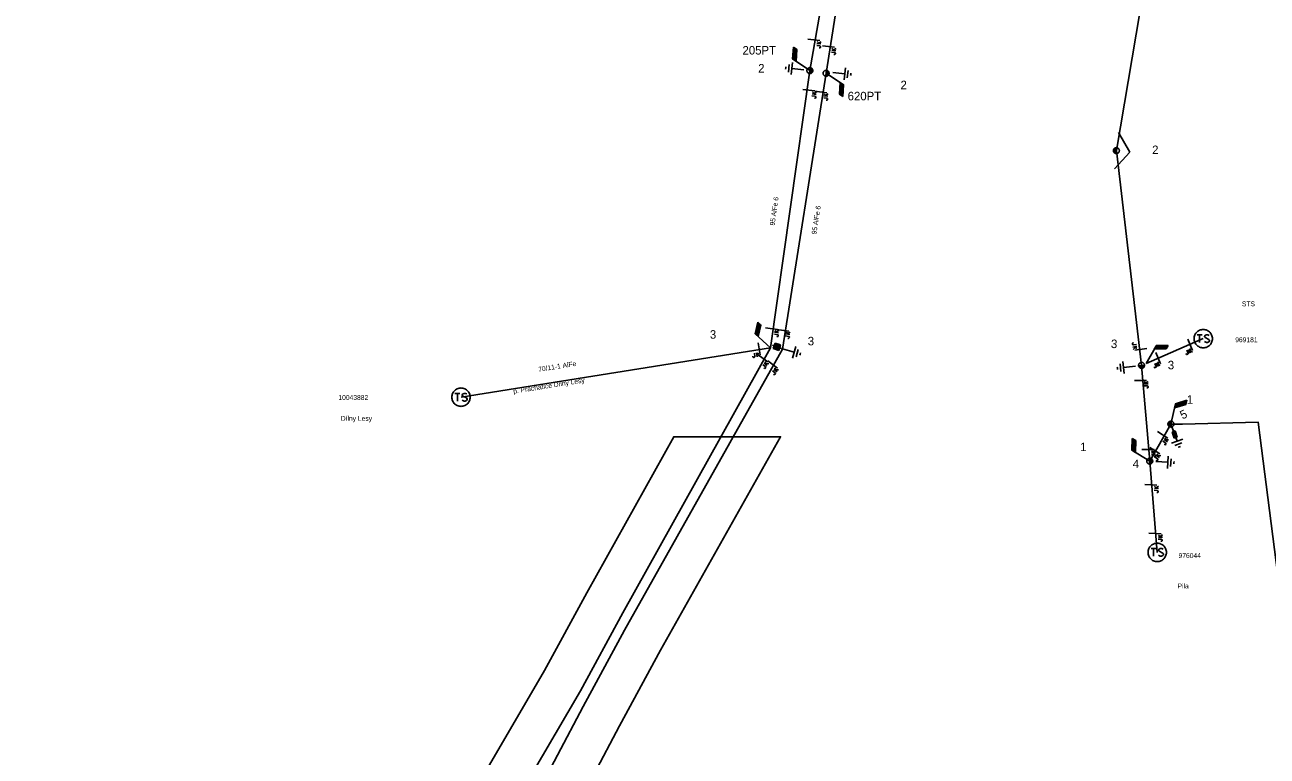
# Model space of a CAD drawing. Extents: x -788491 to -785797, y -1154753 to -1152002.
# Drawn here: x -787760.5 to -787504.8, y -1153999.5 to -1153849 of the extents above; entities that cross this region are included whole.
import ezdxf

# ---------------------------------------------------------------- set-up
doc = ezdxf.new("R2010")
doc.units = 0
for name, color, linetype in [('Default', 7, 'Continuous'), ('Vrstva 1', 7, 'Continuous'), ('Vrstva 11', 7, 'Continuous'), ('Vrstva 12', 7, 'Continuous'), ('Vrstva 13', 7, 'Continuous'), ('Vrstva 14', 7, 'Continuous'), ('Vrstva 15', 7, 'Continuous'), ('Vrstva 16', 7, 'Continuous'), ('Vrstva 18', 7, 'Continuous'), ('Vrstva 2', 7, 'Continuous'), ('Vrstva 25', 7, 'Continuous'), ('Vrstva 26', 7, 'Continuous'), ('Vrstva 27', 7, 'Continuous'), ('Vrstva 35', 7, 'Continuous'), ('Vrstva 4', 7, 'Continuous'), ('Vrstva 5', 7, 'Continuous'), ('Vrstva 52', 7, 'Continuous'), ('Vrstva 57', 7, 'Continuous'), ('Vrstva 59', 7, 'Continuous'), ('Vrstva 6', 7, 'Continuous')]:
    doc.layers.add(name, color=color, linetype=linetype)

# ---------------------------------------------------------------- blocks, each defined once
blk = doc.blocks.new('VN840')
at = {"layer": 'Vrstva 15'}
for points in [[(-0.01, 1.41), (-0.01, -1.09)], [(-1.51, -1.24), (-1.51, -1.15)], [(-1.48, -1.35), (-1.51, -1.24)], [(-1.33, -1.42), (-1.48, -1.35)], [(-1.27, -1.42), (-1.33, -1.42)], [(-1.13, -1.35), (-1.27, -1.42)], [(-1.09, -1.24), (-1.13, -1.35)], [(-1.09, -0.59), (-1.09, -1.24)], [(-0.68, -0.59), (-0.68, -1.42)], [(-0.68, -1.11), (-0.27, -0.59)], [(-0.54, -0.94), (-0.2, -1.42)]]:
    blk.add_lwpolyline(points, dxfattribs=at)
blk = doc.blocks.new('VN860')
at = {"layer": 'Vrstva 15'}
for points in [[(-3.74, 0), (0.01, 2.82)], [(0.01, 2.82), (3.76, 0)]]:
    blk.add_lwpolyline(points, dxfattribs=at)
blk = doc.blocks.new('VN440')
at = {"layer": 'Vrstva 2'}
for points in [[(1.22, 0), (1.21, 0.13), (1.19, 0.25), (1.16, 0.38), (1.11, 0.5), (1.05, 0.61), (0.98, 0.72), (0.9, 0.82), (0.81, 0.91), (0.71, 0.99), (0.6, 1.06), (0.49, 1.12), (0.37, 1.16), (0.25, 1.2), (0.12, 1.22), (-0.01, 1.22), (-0.14, 1.22), (-0.26, 1.2), (-0.39, 1.16), (-0.51, 1.12), (-0.62, 1.06), (-0.73, 0.99), (-0.83, 0.91), (-0.92, 0.82), (-1, 0.72), (-1.07, 0.61), (-1.13, 0.5), (-1.18, 0.38), (-1.21, 0.25), (-1.23, 0.13), (-1.24, 0), (-1.23, -0.13), (-1.21, -0.26), (-1.18, -0.38), (-1.13, -0.5), (-1.07, -0.62), (-1, -0.73), (-0.92, -0.83), (-0.83, -0.92), (-0.73, -1), (-0.62, -1.07), (-0.51, -1.13), (-0.39, -1.17), (-0.26, -1.2), (-0.14, -1.23), (-0.01, -1.23), (0.12, -1.23), (0.25, -1.2), (0.37, -1.17), (0.49, -1.13), (0.6, -1.07), (0.71, -1), (0.81, -0.92), (0.9, -0.83), (0.98, -0.73), (1.05, -0.62), (1.11, -0.5), (1.16, -0.38), (1.19, -0.26), (1.21, -0.13), (1.22, 0)], [(-1.24, 0), (1.22, 0)], [(-1.18, -0.34), (1.1, -0.34)], [(-1.01, -0.63), (0.97, -0.63)], [(-0.74, -0.92), (0.68, -0.92)]]:
    blk.add_lwpolyline(points, dxfattribs=at)
blk = doc.blocks.new('VN820')
at = {"layer": 'Vrstva 13'}
for points in [[(0, 0), (0, -2.1)], [(-0.32, -1.63), (0.34, -1.63)], [(-0.32, -2.95), (-0.32, -1.63)], [(0, -2.1), (-0.12, -1.86)], [(0, -2.1), (0.12, -1.86)], [(0.34, -1.63), (0.34, -2.95)], [(0.34, -2.95), (-0.32, -2.95)], [(0, -2.95), (0, -3.75)]]:
    blk.add_lwpolyline(points, dxfattribs=at)
blk = doc.blocks.new('VN810')
at = {"layer": 'Vrstva 14'}
for points in [[(0, -1.25), (0, -3.75)], [(1.25, -3.75), (-1.25, -3.75)], [(0.77, -4.37), (-0.8, -4.37)], [(0, -5), (-0.25, -5)], [(0.27, -5), (0, -5)]]:
    blk.add_lwpolyline(points, dxfattribs=at)
blk = doc.blocks.new('VN610')
at = {"layer": 'Vrstva 6'}
for points in [[(1.88, 0), (1.87, 0.2), (1.84, 0.39), (1.79, 0.58), (1.72, 0.77), (1.63, 0.94), (1.52, 1.11), (1.4, 1.26), (1.26, 1.4), (1.1, 1.53), (0.94, 1.63), (0.76, 1.72), (0.58, 1.8), (0.39, 1.85), (0.19, 1.88), (-0.01, 1.89), (-0.21, 1.88), (-0.4, 1.85), (-0.59, 1.8), (-0.78, 1.72), (-0.95, 1.63), (-1.12, 1.53), (-1.27, 1.4), (-1.41, 1.26), (-1.54, 1.11), (-1.64, 0.94), (-1.73, 0.77), (-1.8, 0.58), (-1.86, 0.39), (-1.89, 0.2), (-1.9, 0), (-1.89, -0.2), (-1.86, -0.39), (-1.8, -0.58), (-1.73, -0.77), (-1.64, -0.95), (-1.54, -1.11), (-1.41, -1.27), (-1.27, -1.41), (-1.12, -1.53), (-0.95, -1.64), (-0.78, -1.73), (-0.59, -1.8), (-0.4, -1.85), (-0.21, -1.88), (-0.01, -1.89), (0.19, -1.88), (0.39, -1.85), (0.58, -1.8), (0.76, -1.73), (0.94, -1.64), (1.1, -1.53), (1.26, -1.41), (1.4, -1.27), (1.52, -1.11), (1.63, -0.95), (1.72, -0.77), (1.79, -0.58), (1.84, -0.39), (1.87, -0.2), (1.88, 0)], [(-1.27, 0.78), (-0.26, 0.78)], [(-0.76, 0.78), (-0.76, -0.79)], [(1.19, 0.66), (0.94, 0.78), (0.62, 0.78), (0.37, 0.66), (0.24, 0.47), (0.24, 0.4), (0.37, 0.22), (1.12, -0.16), (1.25, -0.32), (1.25, -0.48), (1.12, -0.67), (0.87, -0.79), (0.62, -0.79), (0.49, -0.73), (0.24, -0.6)]]:
    blk.add_lwpolyline(points, dxfattribs=at)
blk = doc.blocks.new('VN001')
at = {"layer": 'Default'}
for p, q in [((1.73, 3.03), (4.14, 3.03)), ((1.76, 3.08), (4.17, 3.08)), ((1.79, 3.13), (4.2, 3.13)), ((1.82, 3.18), (4.23, 3.18)), ((1.85, 3.23), (4.26, 3.23)), ((1.87, 3.28), (4.29, 3.28)), ((1.9, 3.33), (4.32, 3.33)), ((1.93, 3.38), (4.35, 3.38)), ((1.96, 3.43), (4.37, 3.43)), ((1.99, 3.48), (4.4, 3.48)), ((2.02, 3.53), (4.43, 3.53)), ((2.05, 3.58), (4.46, 3.58)), ((2.07, 3.63), (4.49, 3.63)), ((2.1, 3.68), (4.52, 3.68)), ((2.13, 3.73), (2.54, 3.73))]:
    blk.add_line(p, q, dxfattribs=at)
blk.add_lwpolyline([(2.13, 3.73), (0, 0)], dxfattribs=at)
blk.add_lwpolyline([(4.55, 3.73), (2.13, 3.73), (1.7, 2.98), (4.12, 2.99)], close=True, dxfattribs=at)
blk = doc.blocks.new('VN470')
at = {"layer": 'Vrstva 2'}
for points in [[(-1.23, 1.22), (1.23, 1.22)], [(-1.23, -1.23), (-1.23, 1.22)], [(-0.92, 0.9), (0.92, 0.9)], [(-0.92, -0.95), (-0.92, 0.9)], [(-0.61, 0.61), (0.61, 0.61)], [(-0.61, -0.62), (-0.61, 0.61)], [(-0.31, -0.27), (-0.31, 0.34)], [(-0.31, 0.34), (0.31, 0.34)], [(0, 1.22), (0, 1.97)], [(0.31, 0.34), (0.31, -0.27)], [(0.61, 0.61), (0.61, -0.62)], [(0.92, 0.9), (0.92, -0.95)], [(1.23, 1.22), (1.23, -1.23)], [(1.23, -1.23), (-1.23, -1.23)], [(0.92, -0.95), (-0.92, -0.95)], [(0.61, -0.62), (-0.61, -0.62)], [(0.31, -0.27), (-0.31, -0.27)], [(0, -1.23), (0, -1.98)]]:
    blk.add_lwpolyline(points, dxfattribs=at)

msp = doc.modelspace()

# ---------------------------------------------------------------- linework, layer by layer
at = {"layer": 'Vrstva 1'}
for points in [[(-787589.17, -1153802.32), (-787598.94, -1153858.43)], [(-787595.6, -1153858.98), (-787586.72, -1153802.63)], [(-787758.04, -1154108.54), (-787666.77, -1154029.34), (-787645.62, -1153989.29), (-787637.12, -1153973.58), (-787604.57, -1153915.79), (-787595.6, -1153858.98)], [(-787598.94, -1153858.43), (-787607.03, -1153915.49)], [(-787607.03, -1153915.49), (-787637.43, -1153970.03), (-787646.17, -1153986.09), (-787669.6, -1154026.19), (-787760.49, -1154105.76), (-787790.77, -1154129.38), (-787853.74, -1154177.36), (-787944.45, -1154251.81), (-787941.69, -1154348.3), (-787939.33, -1154432.99), (-788019.18, -1154537.71), (-788103.24, -1154647.83), (-788109.69, -1154656.37)]]:
    msp.add_lwpolyline(points, dxfattribs=at)
at = {"layer": 'Vrstva 35'}
msp.add_lwpolyline([(-787629.68, -1153977.68), (-787638.12, -1153993.3), (-787659.25, -1154033.31), (-787659.8, -1154034.2), (-787660.45, -1154035.02), (-787661.2, -1154035.76), (-787752.52, -1154115), (-787752.82, -1154115.25), (-787783.11, -1154138.77), (-787812.59, -1154161.52), (-787816.41, -1154153.73), (-787788.31, -1154132.06), (-787773.97, -1154120.91), (-787774.28, -1154116.51), (-787774.99, -1154106.28), (-787765.91, -1154099.2), (-787676.24, -1154020.71), (-787653.58, -1153981.92), (-787644.88, -1153965.93), (-787626.97, -1153933.8), (-787617.24, -1153933.8), (-787614.72, -1153933.8), (-787604.96, -1153933.8)], close=True, dxfattribs=at)
at = {"layer": 'Vrstva 4'}
for points in [[(-787529.74, -1153918.71), (-787517.96, -1153913.6)], [(-787607.03, -1153915.49), (-787670.74, -1153925.64)], [(-787524.62, -1153931.18), (-787528.99, -1153938.8)], [(-787528.99, -1153938.8), (-787527.43, -1153957.58)]]:
    msp.add_lwpolyline(points, dxfattribs=at)
at = {"layer": 'Vrstva 5'}
msp.add_lwpolyline([(-787524.62, -1153931.18), (-787522.25, -1153931.23), (-787506.67, -1153930.76), (-787500.63, -1153977.83), (-787499.16, -1153981.29), (-787492.91, -1153984.61)], dxfattribs=at)
at = {"layer": 'Vrstva 52'}
for points in [[(-787518.17, -1153765.09), (-787525.35, -1153812.76), (-787535.85, -1153874.91), (-787530.66, -1153919.1)], [(-787530.66, -1153919.1), (-787528.99, -1153938.8)]]:
    msp.add_lwpolyline(points, dxfattribs=at)

# ---------------------------------------------------------------- block references
at = {"layer": 'Vrstva 11'}
for p, rotation in [((-787598.94, -1153858.43), 85.84858051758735), ((-787595.6, -1153858.98), -93.48196114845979), ((-787607.03, -1153915.49), 77.01249689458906), ((-787524.62, -1153931.18), 16.868933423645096), ((-787528.99, -1153938.8), 88.1183110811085)]:
    msp.add_blockref('VN001', p, dxfattribs=dict(at, rotation=rotation))
msp.add_blockref('VN001', (-787529.74, -1153918.71), dxfattribs=at)
at = {"layer": 'Vrstva 13'}
for name, p, xscale, yscale, rotation in [('VN440', (-787598.94, -1153858.43), 0.5, 0.5, 82.96221112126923), ('VN440', (-787595.6, -1153858.98), 0.5000000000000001, 0.4999999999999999, 82.96221113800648), ('VN440', (-787535.85, -1153874.91), 0.5, 0.5, -83.05109166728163), ('VN470', (-787605.73, -1153915.28), 0.5, 0.49999999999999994, -109.23822252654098), ('VN440', (-787530.66, -1153919.1), 0.5000000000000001, 0.5, 6.948908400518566), ('VN440', (-787524.62, -1153931.18), 0.5, 0.5, -64.12912780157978), ('VN440', (-787528.99, -1153938.8), 0.49999999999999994, 0.5000000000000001, 88.1183110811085)]:
    msp.add_blockref(name, p, dxfattribs=dict(at, xscale=xscale, yscale=yscale, rotation=rotation))
at = {"layer": 'Vrstva 15'}
for p, rotation in [((-787598.94, -1153858.43), -96.16292217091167), ((-787595.49, -1153858.68), 83.82793618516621), ((-787605.77, -1153915.37), 73.86162982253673), ((-787530.66, -1153919.1), -83.30144720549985), ((-787524.62, -1153931.18), 20.41705564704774), ((-787528.99, -1153938.8), 86.28621390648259)]:
    msp.add_blockref('VN810', p, dxfattribs=dict(at, rotation=rotation))
at = {"layer": 'Vrstva 16', "rotation": 19.532908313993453}
msp.add_blockref('VN820', (-787524.62, -1153931.18), dxfattribs=at)
at = {"layer": 'Vrstva 18'}
for name, p, rotation in [('VN840', (-787597.99, -1153852.11), 82.96221112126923), ('VN840', (-787594.94, -1153853.5), 82.96221112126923), ('VN840', (-787598.97, -1153862.48), 82.96221112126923), ('VN840', (-787596.54, -1153862.86), 82.96221113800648), ('VN860', (-787535.85, -1153874.91), -96.24503330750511), ('VN840', (-787606.69, -1153911.55), 82.96221113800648), ('VN840', (-787604.38, -1153911.88), 82.1150000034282), ('VN840', (-787609.35, -1153915.86), 8.81316943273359), ('VN840', (-787530.99, -1153915.83), -83.30144720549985), ('VN840', (-787520.58, -1153915.01), 22.840994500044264), ('VN840', (-787608.44, -1153917.74), 53.398111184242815), ('VN840', (-787527.17, -1153917.75), 22.840994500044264), ('VN840', (-787606.44, -1153919.02), 53.39855291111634), ('VN840', (-787530.71, -1153922.21), 89.58176945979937), ('VN840', (-787526.17, -1153933.47), 57.05726943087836), ('VN840', (-787529.19, -1153936.38), 89.58176945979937), ('VN840', (-787527.8, -1153936.73), 57.05726937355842), ('VN840', (-787528.58, -1153943.68), 86.28621390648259), ('VN840', (-787527.75, -1153953.71), 86.28621390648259)]:
    msp.add_blockref(name, p, dxfattribs=dict(at, rotation=rotation))
at = {"layer": 'Vrstva 25', "rotation": 0.06103622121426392}
msp.add_blockref('VN610', (-787517.96, -1153913.6), dxfattribs=at)
at = {"layer": 'Vrstva 25'}
for p in [(-787670.74, -1153925.64), (-787527.43, -1153957.58)]:
    msp.add_blockref('VN610', p, dxfattribs=at)

# ---------------------------------------------------------------- texts
at = {"layer": 'Vrstva 12'}
for s, p in [('205PT', (-787612.8, -1153855.13)), ('620PT', (-787591.16, -1153864.55)), ('3', (-787619.52, -1153913.61)), ('3', (-787525.26, -1153919.91)), ('1', (-787521.34, -1153927)), ('1', (-787543.28, -1153936.74))]:
    msp.add_text(s, height=1.75, dxfattribs=at).set_placement(p)
at = {"layer": 'Vrstva 14'}
for s, p in [('2', (-787609.58, -1153858.83)), ('2', (-787580.28, -1153862.26)), ('2', (-787528.49, -1153875.61)), ('3', (-787599.37, -1153914.98))]:
    msp.add_text(s, height=1.75, dxfattribs=at).set_placement(p)
for s, rotation, p in [('3', 356.625, (-787537.01, -1153915.5)), ('5', 25.871, (-787522.24, -1153930.25)), ('4', 358.118, (-787532.51, -1153940.2))]:
    msp.add_text(s, height=1.75, rotation=rotation, dxfattribs=at).set_placement(p)
at = {"layer": 'Vrstva 2'}
for rotation, p in [(81.989, (-787606.2, -1153890.37)), (81.025, (-787597.61, -1153892.18))]:
    msp.add_text('95 AlFe 6', height=1, rotation=rotation, dxfattribs=at).set_placement(p)
at = {"layer": 'Vrstva 26'}
for s, p in [('969181', (-787511.39, -1153914.33)), ('10043882', (-787695.99, -1153926.21)), ('976044', (-787523.05, -1153958.74))]:
    msp.add_text(s, height=1, dxfattribs=at).set_placement(p)
at = {"layer": 'Vrstva 27'}
msp.add_text('STS', height=1, rotation=0.061, dxfattribs=at).set_placement((-787510.01, -1153906.94))
for s, p in [('Dílny Lesy', (-787695.5, -1153930.51)), ('Pila', (-787523.25, -1153965))]:
    msp.add_text(s, height=1, dxfattribs=at).set_placement(p)
at = {"layer": 'Vrstva 57'}
msp.add_text('70/11-1 AlFe', height=1, rotation=9.03, dxfattribs=at).set_placement((-787654.77, -1153920.43))
at = {"layer": 'Vrstva 59'}
msp.add_text('p. Prachatice Dílny Lesy', height=1, rotation=9.03, dxfattribs=at).set_placement((-787659.93, -1153924.93))

doc.saveas('drawing.dxf')
